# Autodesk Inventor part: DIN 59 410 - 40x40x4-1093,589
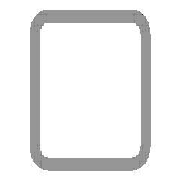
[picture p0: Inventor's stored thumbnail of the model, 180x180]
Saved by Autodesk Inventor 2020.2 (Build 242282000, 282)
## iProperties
Manager: www.cadconsulting.pl
Company: Fabian Stasiak CAD Consulting
IsCustomPart: 1
_CCFamilyMember: 20
_CCFamilyDisplayName: DIN 59410 (Kwadrat) - Rurki stalowe o przekroju kwadratowym formowane na gorąco
_FrameMemberDoc: Frame Member File
_Version: 15.0.0
_GetPNFromCC: 1
Created: 2015-01
Part Number: DIN 59 410 - 40x40x4-1093,589
Material: Stal, miękka
Description: Rurki stalowe o przekroju kwadratowym formowane na gorąco
Document SubType Name: Modellieren
Standard: DIN
Designer: F.Stasiak
Standards Organization: DIN
Language: pl-PL
Size Designation: 40x40x4
Categories: <MemberInstance><Categories><Category DisplayName="Kształtowniki konstrukcyjne" InternalName="089c4875-fa83-4c05-b084-43b9cc11f5ed" Mnemonic="GRDR"><CategoryPar
Stock Number: 40x40x4
Density: 7.85 g/cm^3
Appearance: Częściowo polerowana
Mass: 4423.13 g
Surface Area: 2832.4 cm^2
Volume: 563.456 cm^3
Catalog Web Link: www.expertbooks.pl
G_W: 40,000 mm
G_H: 40,000 mm
+AB65C4A5-C569-42BD-9C94-95DBAE06198D+CUTDETAIL1: Wytnij
+4E08C558-0C67-4AA5-93E9-3C11DF237003+CUTDETAIL2: Wytnij
G_L: 1093,589 mm
Author: F.Stasiak
Subject: Zbiór ćwiczeń. Autodesk Inventor 2020. Kurs Professional
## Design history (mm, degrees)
node "Płaszczyzna początkowa"
node "Płaszczyzna końcowa"
sketch "Szkic1"
  geometry: L1 (-12, 20)-(12, 20); L2 (20, 12)-(20, -12); L3 (12, -20)-(-12, -20); L4 (-20, -12)-(-20, 12); L5 (-30.32, 0)-(30.32, 0) reference; L6 (0, -30.32)-(0, 30.32) reference; L7 (-12, 16)-(12, 16); L8 (16, 12)-(16, -12); L9 (12, -16)-(-12, -16); L10 (-16, -12)-(-16, 12); A1 r 8 centre (-12, 12) between (-12, 20) and (-20, 12); A2 r 8 centre (12, 12) between (20, 12) and (12, 20); A3 r 8 centre (12, -12) between (12, -20) and (20, -12); A4 r 8 centre (-12, -12) between (-20, -12) and (-12, -20); A5 r 4 centre (-12, 12) between (-12, 16) and (-16, 12); A6 r 4 centre (12, 12) between (16, 12) and (12, 16); A7 r 4 centre (12, -12) between (12, -16) and (16, -12); A8 r 4 centre (-12, -12) between (-16, -12) and (-12, -16); 3 further points
  constraints: 16 end point, 16 point on circle, 8 centre point, 8 tangent, 6 point on line, 4 parallel, 3 equal radius, 3 perpendicular, 1 horizontal, 7 other
  dimensions: "b" = 40 distance of point (-20, 20) point (20, 20); "msp_r" = 8 radius of A1 (= 2 x ParT); "d8" = 20 distance between parallel lines of L4 L6 (= d9); "d9" = 20 distance between parallel lines of L3 L5 (= 0.5 x b); "d10" = 4 distance between parallel lines of L3 L9 (= ParT)
extrude "Bryła" new body sketch "Szkic1" taper "d4" = 0 deg; stored distance "NLG" = 10
node "Driven Length"
  sketch "Sketch2"
    geometry: L1 (0, 0)-(10, 0) reference
    constraints: 2 end point, 1 horizontal
  workplane "Work Plane3"
  sketch "Sketch3"
    geometry: L1 (-2, 15.355)-(12, 15.355) reference; L2 (-2, 1108.944)-(12, 1108.944) reference
    dimensions: "d14" = 1093.5891 distance between parallel lines of L1 L2 (derived)
node "Płaszczyzna konstrukcyjna4"
feature "Podział1"
node "Płaszczyzna konstrukcyjna5"
feature "Podział2"
body "Solid1"
other parameters: "ParT" = 4, "G_OFFSET_START" = -15.35534 [user parameter; used in 1 equation term], "G_OFFSET_END" = -22.42641 [user parameter; used in 1 equation term], "d11" = 15.35534 (= -G_OFFSET_START), "d12" = 1108.94444 (= G_OFFSET_END + B_L), "G_L" = 1093.5891 (= d14) [user parameter], "B_L" = 1131.37085 [user parameter; used in 1 equation term], "d13" = 90 deg
